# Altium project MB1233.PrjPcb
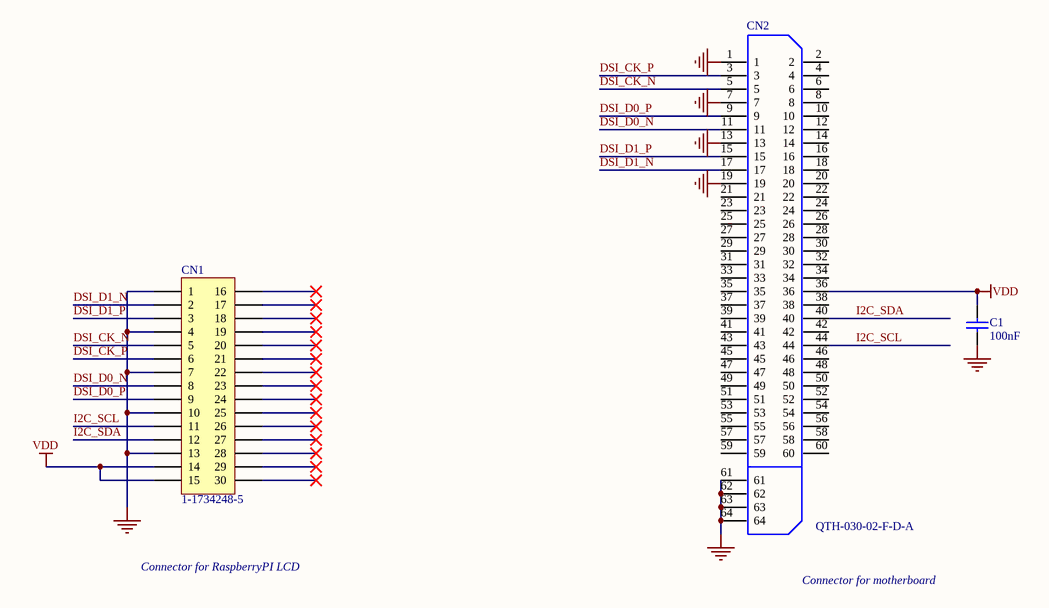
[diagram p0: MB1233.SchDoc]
1 sheet, 3 parts. Net scope: global (net labels, ports and power ports of the same name join across sheets).
Board file: MB1233.PcbDoc

## Sheet MB1233.SchDoc: Overview
size A4; DocumentNumber: MB1233; Revision: A.1; SheetNumber: 1; SheetTotal: 1; Project: RaspberryPI Adapter

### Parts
C1  100nF  [0603C]
CN1  1-1734248-5  [1-1734248-5-SMT]
CN2  QTH-030-02-F-D-A  [QTH-030-02-F-D-A]

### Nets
GND: C1.1 CN1.1 CN1.4 CN1.7 CN1.10 CN1.13 CN2.1 CN2.7 CN2.13 CN2.19 CN2.61 CN2.62 CN2.63 CN2.64
VDD: C1.2 CN1.14 CN1.15 CN2.36
DSI_CK_N: CN1.5 CN2.5
DSI_CK_P: CN1.6 CN2.3
DSI_D0_N: CN1.8 CN2.11
DSI_D0_P: CN1.9 CN2.9
DSI_D1_N: CN1.2 CN2.17
DSI_D1_P: CN1.3 CN2.15
I2C_SCL: CN1.11 CN2.44
I2C_SDA: CN1.12 CN2.40

Not connected (* = marked no-connect by the designer): CN1 16* 17* 18* 19* 20* 21* 22* 23* 24* 25* 26* 27* 28* 29* 30*; CN2 2 4 6 8 10 12 14 16 18 20 21 22 23 24 25 26 27 28 29 30 31 32 33 34 35 37 38 39 41 42 43 45 46 47 48 49 50 51 52 53 54 55 56 57 58 59 60

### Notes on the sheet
- Connector for RaspberryPI LCD
- Connector for motherboard

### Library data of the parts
C1 = CAP: Capacitor; Value: 100pF
CN1 = Header 15X2A: Header, 15-Pin, Dual row
CN2 = QTH-030-02-F-D-A: HIGH SPEED TERMINAL STRIP, .5mm PITCH, 60 PINS.; MANUFACTURER: SAMTEC; PCB DECAL: QTH-030-02-X-D-A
